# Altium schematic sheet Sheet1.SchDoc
size A2
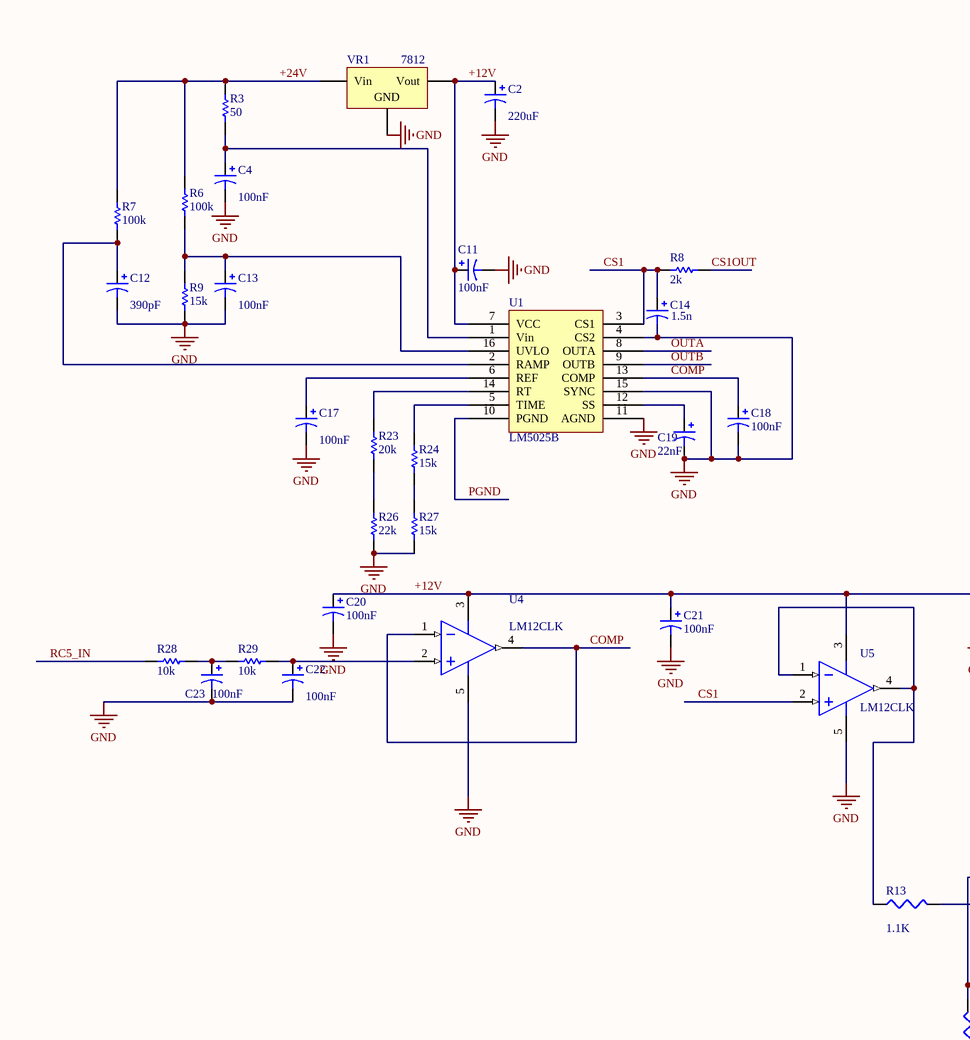
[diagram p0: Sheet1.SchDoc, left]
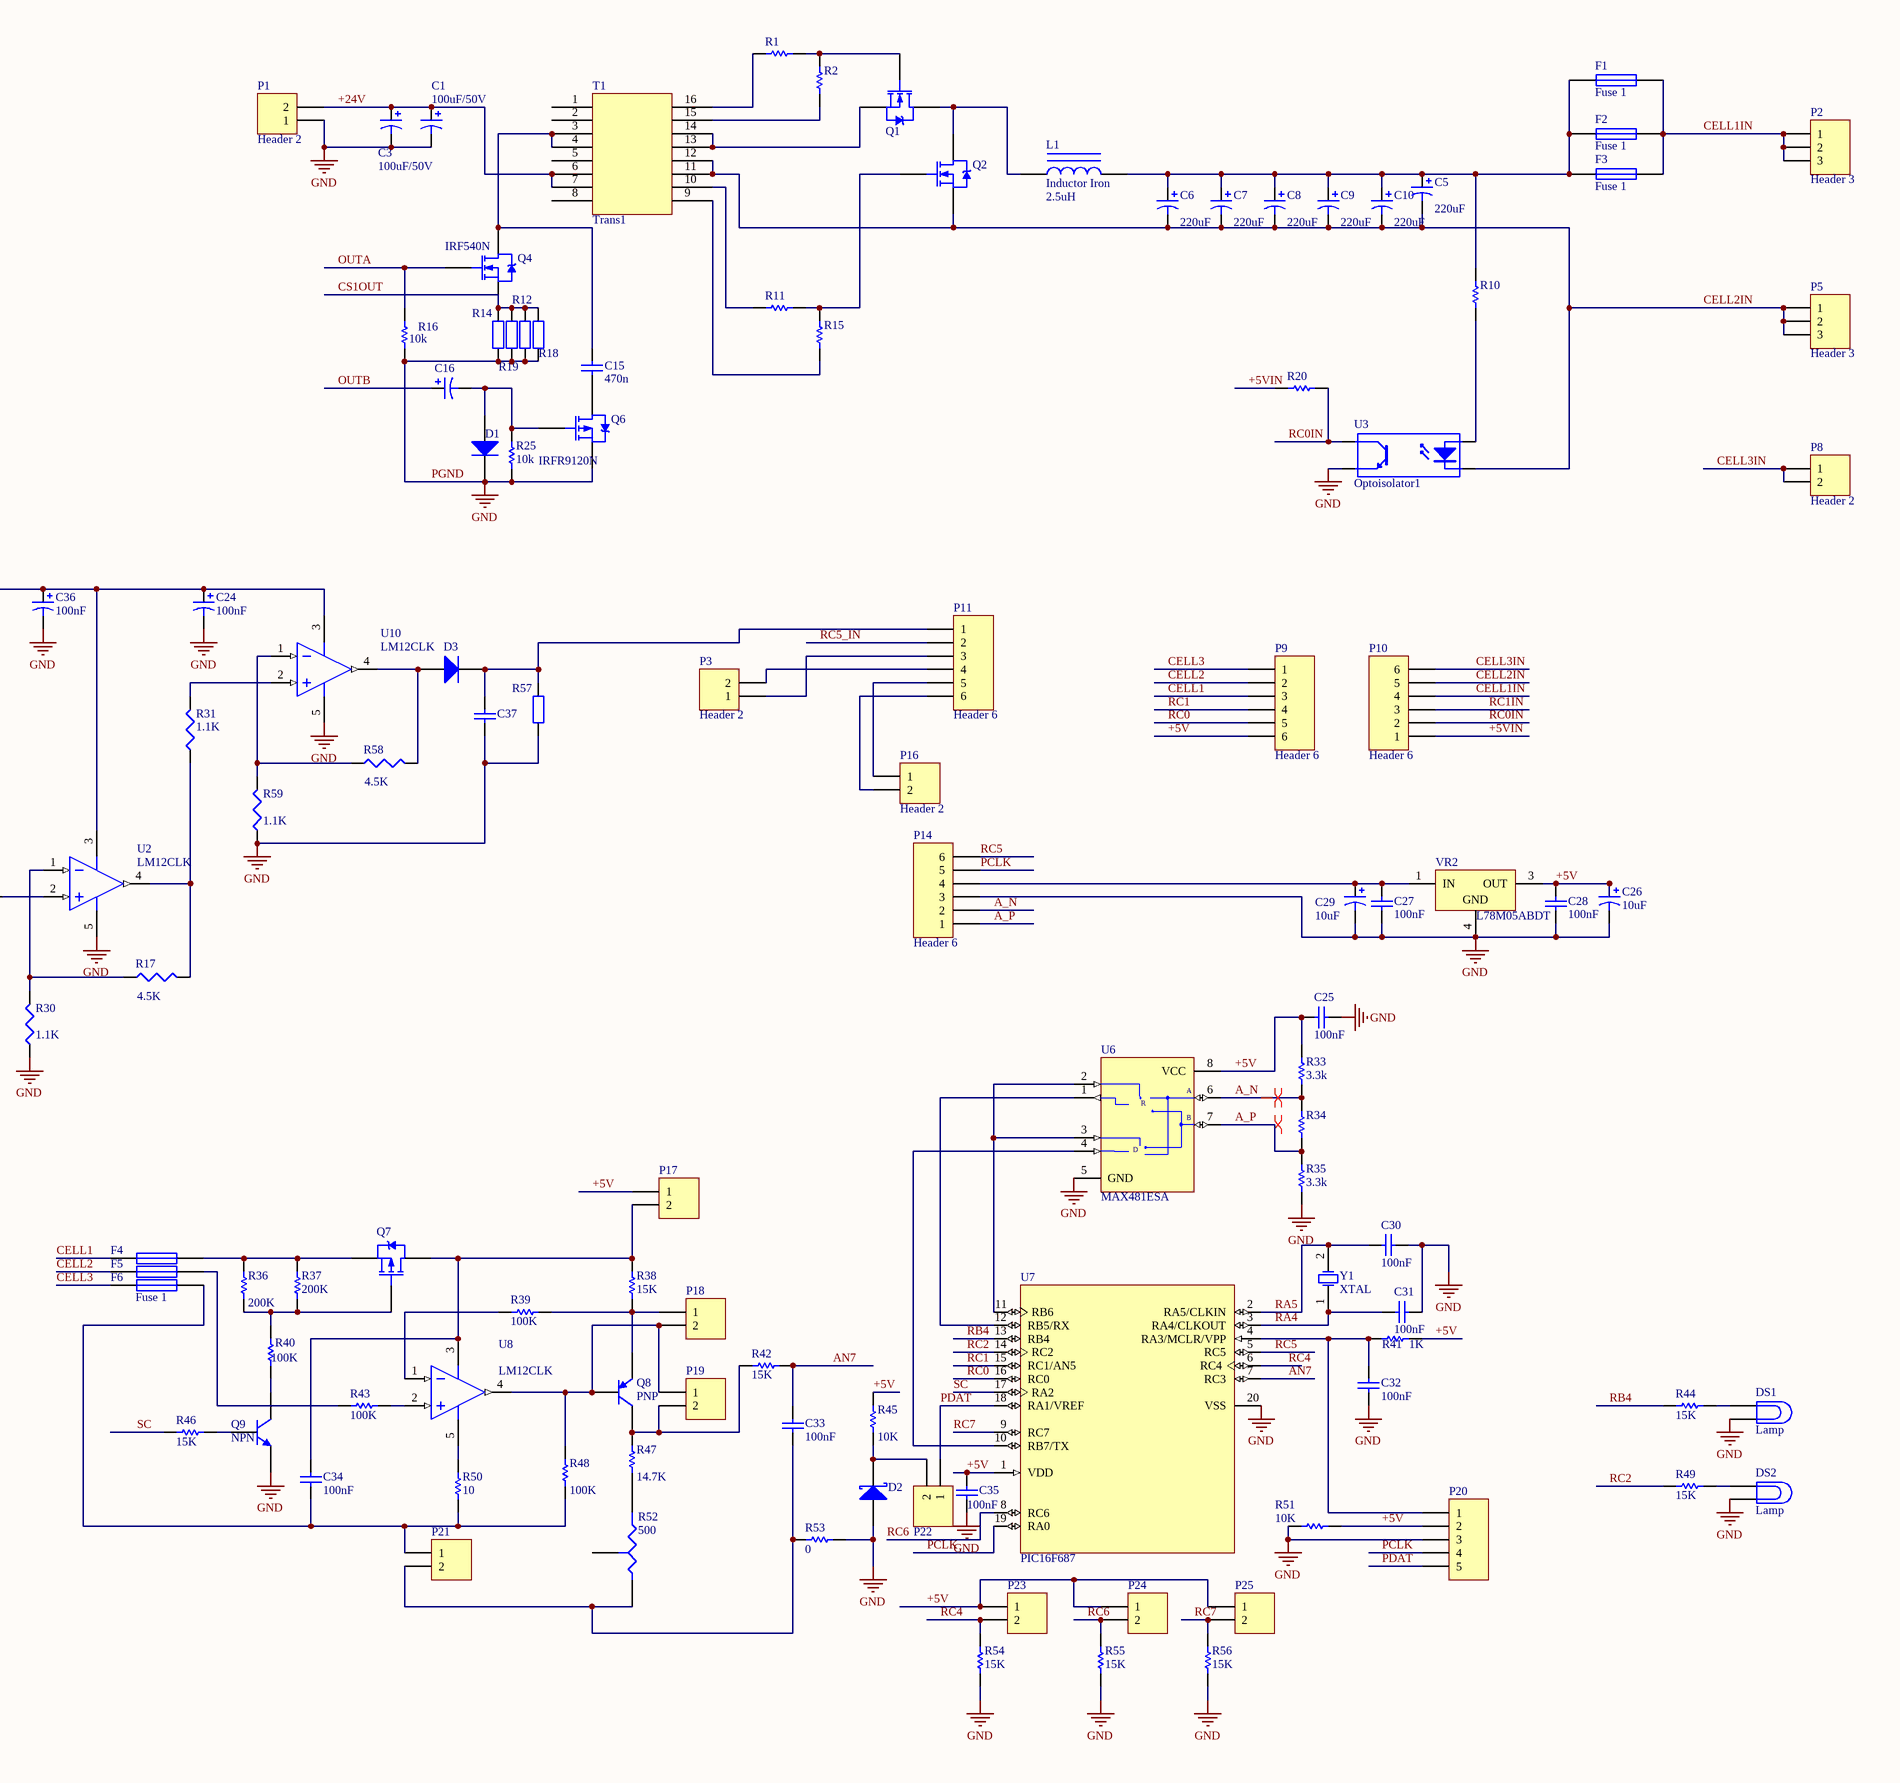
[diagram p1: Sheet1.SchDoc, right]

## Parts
C1  value 100uF/50V  [CAP6]  (hidden comment: Cap Pol1)
C2  value 220uF  [CAPPR5-5x5]  (hidden comment: Cap Pol3)
C3  value 100uF/50V  [CAP6]  (hidden comment: Cap Pol1)
C4  value 100nF  [C0805]  (hidden comment: Cap Pol3)
C5  value 220uF  [CAP5]  (hidden comment: Cap Pol1)
C6  value 220uF  [CAP5]  (hidden comment: Cap Pol1)
C7  value 220uF  [CAP5]  (hidden comment: Cap Pol1)
C8  value 220uF  [CAP5]  (hidden comment: Cap Pol1)
C9  value 220uF  [CAP5]  (hidden comment: Cap Pol1)
C10  value 220uF  [CAP5]  (hidden comment: Cap Pol1)
C11  value 100nF  [C0805]  (hidden comment: Cap Pol3)
C12  value 390pF  [C0805]  (hidden comment: Cap Pol3)
C13  value 100nF  [C0805]  (hidden comment: Cap Pol3)
C14  value 1.5n  [C0805]  (hidden comment: Cap Pol3)
C15  value 470n  [VP45-3.2]  (hidden comment: Cap)
C16  Cap Pol3  [C0805]  (value not drawn)
C17  value 100nF  [C0805]  (hidden comment: Cap Pol3)
C18  value 100nF  [C0805]  (hidden comment: Cap Pol3)
C19  value 22nF  [C0805]  (hidden comment: Cap Pol3)
C20  value 100nF  [C0805]  (hidden comment: Cap Pol3)
C21  value 100nF  [C0805]  (hidden comment: Cap Pol3)
C22  value 100nF  [C0805]  (hidden comment: Cap Pol3)
C23  value 100nF  [C0805]  (hidden comment: Cap Pol3)
C24  value 100nF  [C0805]  (hidden comment: Cap Pol3)
C25  value 100nF  [2012[0805]]  (hidden comment: Cap)
C26  value 10uF  [CAPPR5-5x5]  (hidden comment: Cap Pol1)
C27  value 100nF  [2012[0805]]  (hidden comment: Cap)
C28  value 100nF  [2012[0805]]  (hidden comment: Cap)
C29  value 10uF  [CAPPR5-5x5]  (hidden comment: Cap Pol1)
C30  value 100nF  [2012[0805]]  (hidden comment: Cap)
C31  value 100nF  [2012[0805]]  (hidden comment: Cap)
C32  value 100nF  [2012[0805]]  (hidden comment: Cap)
C33  value 100nF  [CAPPR5-5x5]  (hidden comment: Cap)
C34  value 100nF  [2012[0805]]  (hidden comment: Cap)
C35  value 100nF  [2012[0805]]  (hidden comment: Cap)
C36  value 100nF  [C0805]  (hidden comment: Cap Pol3)
C37  Cap  [VP45-3.2]  (value not drawn)
D1  Diode 1N4934  [DO-41]  (value not drawn)
D2  D Schottky  [SOT23]  (value not drawn)
D3  Diode 1N4934  [DO-41]  (value not drawn)
DS1  Lamp  [PIN2]
DS2  Lamp  [PIN2]
F1  Fuse 1  [fuse30A]
F2  Fuse 1  [fuse30A]
F3  Fuse 1  [fuse30A]
F4  Fuse 1  [6-0805]  (value not drawn)
F5  Fuse 1  [6-0805]  (value not drawn)
F6  Fuse 1  [6-0805]
L1  Inductor Iron  value 2.5uH  [L_circle]
P1  Header 2  [T2]
P2  Header 3  [PIN3]
P3  Header 2  [T2]
P5  Header 3  [PIN3]
P8  Header 2  [T2]
P9  Header 6  [HDR1X6]
P10  Header 6  [HDR1X6]
P11  Header 6  [HDR1X6]
P14  Header 6  [HDR1X6]
P16  Header 2  [T2]
P17  Header 2  [HDR1X2]  (value not drawn)
P18  Header 2  [HDR1X2]  (value not drawn)
P19  Header 2  [HDR1X2]  (value not drawn)
P20  Header 5  [HDR1X5]  (value not drawn)
P21  Header 2  [HDR1X2]  (value not drawn)
P22  Header 2  [HDR1X2]  (value not drawn)
P23  Header 2  [HDR1X2]  (value not drawn)
P24  Header 2  [HDR1X2]  (value not drawn)
P25  Header 2  [HDR1X2]  (value not drawn)
Q1  (no value)  [TO-220AB]
Q2  (no value)  [TO-220AB]
Q4  IRF540N  [TO-220AB]
Q6  IRFR9120N  [TO-252AA]
Q7  PMOS-2  [SOT23]  (value not drawn)
Q8  PNP  [2SB1238]
Q9  NPN  [SOT23]
R1  Res Semi  [2012[0805]]  (value not drawn)
R2  Res Semi  [2012[0805]]  (value not drawn)
R3  value 50  [2012[0805]]  (hidden comment: Res Semi)
R6  value 100k  [2012[0805]]  (hidden comment: Res Semi)
R7  value 100k  [2012[0805]]  (hidden comment: Res Semi)
R8  value 2k  [2012[0805]]  (hidden comment: Res Semi)
R9  value 15k  [2012[0805]]  (hidden comment: Res Semi)
R10  Res Semi  [2012[0805]]  (value not drawn)
R11  Res Semi  [2012[0805]]  (value not drawn)
R12  Res2  [AXIAL-0.4]  (value not drawn)
R13  value 1.1K  [2012[0805]]  (hidden comment: Res3)
R14  Res2  [AXIAL-0.4]  (value not drawn)
R15  Res Semi  [2012[0805]]  (value not drawn)
R16  value 10k  [2012[0805]]  (hidden comment: Res Semi)
R17  value 4.5K  [2012[0805]]  (hidden comment: Res3)
R18  Res2  [AXIAL-0.4]  (value not drawn)
R19  Res2  [AXIAL-0.4]  (value not drawn)
R20  Res Semi  [2012[0805]]  (value not drawn)
R23  value 20k  [2012[0805]]  (hidden comment: Res Semi)
R24  value 15k  [2012[0805]]  (hidden comment: Res Semi)
R25  value 10k  [2012[0805]]  (hidden comment: Res Semi)
R26  value 22k  [2012[0805]]  (hidden comment: Res Semi)
R27  value 15k  [2012[0805]]  (hidden comment: Res Semi)
R28  value 10k  [2012[0805]]  (hidden comment: Res Semi)
R29  value 10k  [2012[0805]]  (hidden comment: Res Semi)
R30  value 1.1K  [2012[0805]]  (hidden comment: Res3)
R31  value 1.1K  [2012[0805]]  (hidden comment: Res3)
R33  value 3.3k  [2012[0805]]  (hidden comment: Res Semi)
R34  Res Semi  [2012[0805]]  (value not drawn)
R35  value 3.3k  [2012[0805]]  (hidden comment: Res Semi)
R36  value 200K  [2012[0805]]  (hidden comment: Res Semi)
R37  value 200K  [2012[0805]]  (hidden comment: Res Semi)
R38  value 15K  [2012[0805]]  (hidden comment: Res Semi)
R39  value 100K  [2012[0805]]  (hidden comment: Res Semi)
R40  value 100K  [2012[0805]]  (hidden comment: Res Semi)
R41  value 1K  [2012[0805]]  (hidden comment: Res Semi)
R42  value 15K  [2012[0805]]  (hidden comment: Res Semi)
R43  value 100K  [2012[0805]]  (hidden comment: Res Semi)
R44  value 15K  [2012[0805]]  (hidden comment: Res Semi)
R45  value 10K  [2012[0805]]  (hidden comment: Res Semi)
R46  value 15K  [2012[0805]]  (hidden comment: Res Semi)
R47  value 14.7K  [2012[0805]]  (hidden comment: Res Semi)
R48  value 100K  [2012[0805]]  (hidden comment: Res Semi)
R49  value 15K  [2012[0805]]  (hidden comment: Res Semi)
R50  value 10  [2012[0805]]  (hidden comment: Res Semi)
R51  value 10K  [2012[0805]]  (hidden comment: Res Semi)
R52  value 500  [VR5]  (hidden comment: Res Tap)
R53  value 0  [2012[0805]]  (hidden comment: Res Semi)
R54  value 15K  [2012[0805]]  (hidden comment: Res Semi)
R55  value 15K  [2012[0805]]  (hidden comment: Res Semi)
R56  value 15K  [2012[0805]]  (hidden comment: Res Semi)
R57  Res2  [AXIAL-0.4]  (value not drawn)
R58  value 4.5K  [2012[0805]]  (hidden comment: Res3)
R59  value 1.1K  [2012[0805]]  (hidden comment: Res3)
T1  Trans1  [DIP16]
U1  LM5025B  [TSSOP16]
U2  LM12CLK  [MA05A]
U3  Optoisolator1  [DIP-4]
U4  LM12CLK  [MA05A]
U5  LM12CLK  [MA05A]
U6  MAX481ESA  [DIP-8]
U7  PIC16F687  [PDIP300-20]
U8  LM12CLK  [MA05A]
U10  LM12CLK  [MA05A]
VR1  Publisher: 7812  [TO-220-AB]  (hidden comment: Volt Reg)
VR2  L78M05ABDT  [TO-252]
Y1  XTAL  [BCY-W2/E4.7]

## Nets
PGND: C1.2 C2.2 C3.2 C4.2 C11.2 C12.2 C13.2 C14.2 C17.2 C18.2 C19.2 C20.2 C21.2 C22.2 C23.2 C24.2 C25.1 C26.2 C27.2 C28.2 C29.2 C30.1 C31.1 C32.1 C35.1 C36.2 C37.1 D1.2(K) D2.1(A) DS1.2 DS2.2 P1.1 P14.3 P20.3 Q6.3(S) Q9.3(E) R9.1 R12.1 R14.1 R16.1 R18.1 R19.1 R25.1 R26.1 R27.1 R30.1 R35.2 R51.2 R53.1 R54.1 R55.1 R56.1 R57.1 R59.1 U1.4(CS2) U1.10(PGND) U1.11(AGND) U1.15(SYNC) U2.5(V-) U3.3(E) U4.5(V-) U5.5(V-) U6.5(GND) U7.20(VSS) U10.5(V-) VR1.2(GND) VR2.4(GND)  [also labelled GND]
+5V: C25.2 C26.1 C28.1 C35.2 P9.6 P17.1 P20.2 P23.1 P24.1 P25.1 R33.1 R41.2 R45.2 R51.1 U6.8(VCC) U7.1(VDD) VR2.3(OUT)
+5VIN: P10.1 R20.1
+12V: C2.1 C11.1 C20.1 C21.1 C24.1 C36.1 U1.7(VCC) U2.3(V+) U4.3(V+) U5.3(V+) U10.3(V+) VR1.3(Vout)
+24V: C1.1 C3.1 P1.2 R3.2 R6.2 R7.2 T1.6 T1.7 VR1.1(Vin)
A_N: P14.2 R33.2 R34.1 U6.6(A)
A_P: P14.1 R34.2 R35.1 U6.7(B)
AN7: C33.1 R42.1 U7.7(RC3)
CELL1: F4.1 P9.3
CELL1IN: F1.2 F2.2 F3.2 P2.1 P2.2 P2.3 P10.4
CELL2: F5.1 P9.2
CELL2IN: C5.2 C6.2 C7.2 C8.2 C9.2 C10.2 P5.1 P5.2 P5.3 P10.5 Q2.3(S) T1.11 T1.12 U3.2(K)
CELL3: F6.1 P9.1
CELL3IN: P8.1 P8.2 P10.6
COMP: C18.1 U1.13(COMP) U4.1(IN-) U4.4(OUT)
CS1: C14.1 R8.2 U1.3(CS1) U5.2(IN+)
CS1OUT: Q4.3(S) R8.1 R12.2 R14.2 R18.2 R19.2
OUTA: Q4.1(G) R16.2 U1.8(OUTA)
OUTB: C16.1 U1.9(OUTB)
PCLK: P14.5 P20.4 U7.19(RA0)
PDAT: P20.5 P22.1 U7.18(RA1/VREF)
RA4: C31.2 U7.3(RA4/CLKOUT) Y1.1(OSC1)
RA5: C30.2 U7.2(RA5/CLKIN) Y1.2(OSC2)
RB4: R44.1 U7.13(RB4)
RC0: P9.5 U7.16(RC0)
RC0IN: P10.2 R20.2 U3.4(C)
RC1: P9.4 U7.15(RC1/AN5)
RC1IN: P10.3
RC2: R49.1 U7.14(RC2)
RC4: P23.2 R54.2 U7.6(RC4)
RC5: P14.6 U7.5(RC5)
RC5_IN: P11.2 R28.2
RC6: P24.2 R55.2 U7.8(RC6)
RC7: P25.2 R56.2 U7.9(RC7)
SC: R46.2 U7.17(RA2)
NetC4_1: C4.1 R3.1 U1.1(Vin)
NetC5_1: C5.1 C6.1 C7.1 C8.1 C9.1 C10.1 F1.1 F2.1 F3.1 L1.2 R10.2
NetC12_1: C12.1 R7.1 U1.2(RAMP)
NetC13_1: C13.1 R6.1 R9.2 U1.16(UVLO)
NetC15_1: C15.1 Q6.4(D)
NetC15_2: C15.2 Q4.2(D) T1.3 T1.4
NetC16_2: C16.2 D1.1(A) Q6.1(G) R25.2
NetC17_1: C17.1 U1.6(REF)
NetC19_1: C19.1 U1.12(SS)
NetC22_1: C22.1 R29.1 U4.2(IN+)
NetC23_1: C23.1 R28.1 R29.2
NetC27_1: C27.1 C29.1 P14.4 VR2.1(IN)
NetC32_2: C32.2 P20.1 R41.1 U7.4(RA3/MCLR/VPP)
NetC33_2: C33.2 P21.2 R52.1(A) R53.2
NetC34_1: C34.1 F6.2 P21.1 R48.1 R50.1
NetC34_2: C34.2 P17.2 Q7.2(D) R38.2 U8.3(V+)
NetC37_2: C37.2 D3.2(K) P11.1 R57.2
NetD2_2: D2.2(K) P22.2 R45.1
NetD3_1: D3.1(A) R58.2 U10.4(OUT)
NetDS1_1: DS1.1 R44.2
NetDS2_1: DS2.1 R49.2
NetF4_2: F4.2 Q7.3(S) R36.2 R37.2
NetF5_2: F5.2 R43.2
NetL1_1: L1.1 Q1.2(D) Q2.2(D)
NetP3_1: P3.1 P11.3
NetP3_2: P3.2 P11.4
NetP11_5: P11.5 P16.1
NetP11_6: P11.6 P16.2
NetP18_1: P18.1 Q8.3(E) R38.1 R39.1
NetP18_2: P18.2 P19.1 Q8.2(B) R48.2 U8.4(OUT)
NetP19_2: P19.2 Q8.1(C) R42.2 R47.2
NetQ1_1: Q1.1(G) R1.2 R2.2
NetQ1_3: Q1.3(S) T1.13 T1.14
NetQ2_1: Q2.1(G) R11.1 R15.2
NetQ7_1: Q7.1(G) R36.1 R37.1 R40.2
NetQ9_1: Q9.1(C) R40.1
NetQ9_2: Q9.2(B) R46.1
NetR1_1: R1.1 T1.16
NetR2_1: R2.1 T1.15
NetR10_1: R10.1 U3.1(A)
NetR11_2: R11.2 T1.10
NetR13_1: R13.1 U5.1(IN-) U5.4(OUT)
NetR13_2: R13.2 U2.2(IN+)
NetR15_1: R15.1 T1.9
NetR17_1: R17.1 R30.2 U2.1(IN-)
NetR17_2: R17.2 R31.1 U2.4(OUT)
NetR23_1: R23.1 R26.2
NetR23_2: R23.2 U1.14(RT)
NetR24_1: R24.1 R27.2
NetR24_2: R24.2 U1.5(TIME)
NetR31_2: R31.2 U10.2(IN+)
NetR39_2: R39.2 U8.1(IN-)
NetR43_1: R43.1 U8.2(IN+)
NetR47_1: R47.1 R52.2(B)
NetR50_2: R50.2 U8.5(V-)
NetR58_1: R58.1 R59.2 U10.1(IN-)
NetU6_1: U6.1(RO) U7.12(RB5/RX)
NetU6_2: U6.2(~{RE}) U6.3(DE) U7.11(RB6)
NetU6_4: U6.4(DI) U7.10(RB7/TX)

Not connected (* = marked no-connect by the designer): R52 3(TAP); T1 1 2 5 8

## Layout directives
differential pair: A_N, A_P

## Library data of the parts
C1 C3 C5-C10 C26 C29 = Cap Pol1: Polarized Capacitor (Radial)
C2 C4 C11-C14 C16-C24 C36 = Cap Pol3: Polarized Capacitor (Surface Mount)
C15 C25 C27 C28 C30-C35 C37 = Cap: Capacitor
D1 D3 = Diode 1N4934: 1 Amp Fast Recovery Rectifier
D2 = D Schottky: Schottky Diode; pin to pad: 1>2 2>3
DS1 DS2 = Lamp: Incandescent Bulb
F1-F6 = Fuse 1: Fuse
L1 = Inductor Iron: Magnetic-Core Inductor
P1 P8 P17-P19 P21-P25 = Header 2: Header, 2-Pin
P2 P5 = Header 3: Header, 3-Pin
P3 P16 = Header 2: Header, 2-Pin; pin to pad: 1>2 2>1
P9-P11 P14 = Header 6: Header, 6-Pin
P20 = Header 5: Header, 5-Pin
Q1 Q2 Q4 = IRF540N: HEXFET Power MOSFET; Note: Pin 2 is electrically connected to pin 4.; Sim Note: Thermal Model provided is not called on from main Subckt.
Q6 = IRFR9120N: HEXFET Power MOSFET; Note: Pin 2 is trimmed and is electrically connected to Drain.
Q7 = PMOS-2: P-Channel Power MOSFET; pin to pad: 1>3 2>1 3>2; Note: Pin 4 not drawn and electrically connected to Pin 2.
Q8 = PNP: PNP Bipolar Transistor; pin to pad: 1>2 2>3 3>1
Q9 = NPN: NPN Bipolar Transistor; pin to pad: 2>3 3>2
R1 R2 R10 R11 R15 R20 = Res Semi: Semiconductor Resistor; Value: 1K
R3 R6-R9 R16 R23-R29 R33 R35-R51 R53-R56 = Res Semi: Semiconductor Resistor
R12 R14 R18 R19 R57 = Res2: Resistor
R13 R17 R30 R31 R58 R59 = Res3: Resistor
R34 = Res Semi: Semiconductor Resistor; Value: 10K
R52 = Res Tap: Tapped Resistor; Sim Note: Enter the Resistance value and the set point into parameter fields.; Set Position: 0.5
U2 U4 U5 U8 U10 = LM12CLK: 80W Operational Amplifier; pin to pad: 1>3 2>1 3>5 5>2; Note: Pin 5 is case ( V-).
U3 = Optoisolator1: 4-Pin Phototransistor Optocoupler
U6 = MAX481ESA: Low-Power, Slew-Rate-Limited RS-485/RS-422 Transceiver
VR1 = Volt Reg: Voltage Regulator
VR2 = L78M05ABDT: Precision 500mA Regulator
Y1 = XTAL: Crystal Oscillator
